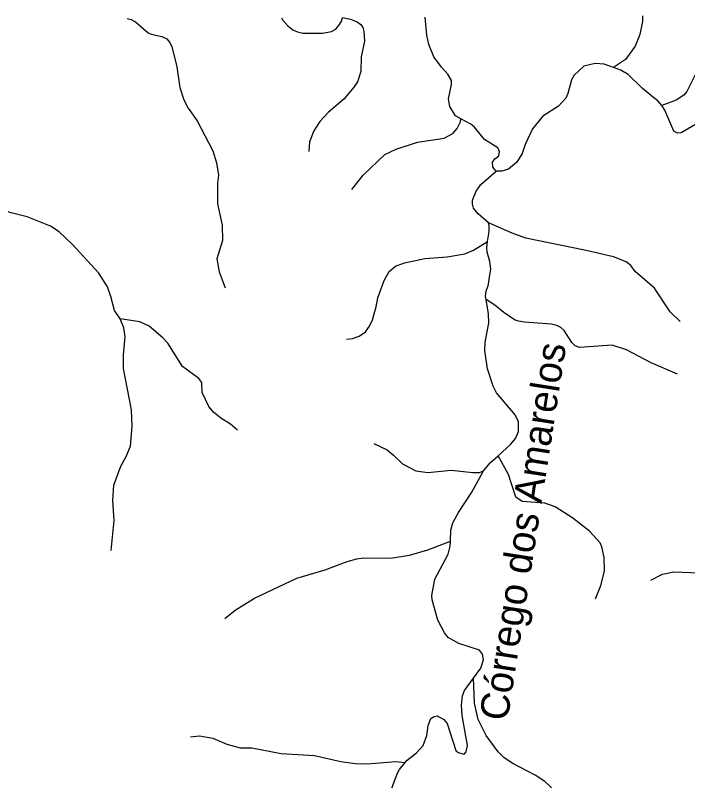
# Model space of a CAD drawing. Extents: x 280.4 to 335.6, y 8893.9 to 8949.5.
# Drawn here: x 293.02 to 297.74, y 8943.96 to 8949.33 of the extents above; entities that cross this region are included whole.
import ezdxf
from ezdxf.enums import TextEntityAlignment as Align

# ---------------------------------------------------------------- set-up
doc = ezdxf.new("R2010")
doc.units = 0
doc.header["$LTSCALE"] = 0.064
doc.linetypes.add('LONG_DASHED', pattern=[7.5, 6, -1.5])
doc.layers.add('61', color=7, linetype='Continuous')
doc.layers.add('7', color=7, linetype='Continuous', lineweight=25)
doc.layers.add('9', color=7, linetype='LONG_DASHED', lineweight=25)

msp = doc.modelspace()

# ---------------------------------------------------------------- linework, layer by layer
at = {"layer": '7'}
for points in [[(293.8085, 8949.3069), (293.8352, 8949.3008), (293.867, 8949.2831), (293.9552, 8949.2082), (293.9757, 8949.1983), (294.052, 8949.1811), (294.0872, 8949.1649), (294.1049, 8949.1417), (294.1208, 8949.1109), (294.1572, 8948.9685), (294.1769, 8948.8231), (294.2053, 8948.7373), (294.2352, 8948.6778), (294.2982, 8948.5895), (294.4092, 8948.3801), (294.4358, 8948.2952), (294.4485, 8948.2089), (294.4423, 8948.152), (294.4425, 8948.0083), (294.4755, 8947.8586), (294.4775, 8947.7513), (294.4376, 8947.622), (294.4535, 8947.5309), (294.4951, 8947.4173)], [(294.8909, 8949.3127), (294.9005, 8949.2957), (294.9349, 8949.256), (294.97, 8949.2278), (295.0028, 8949.2131), (295.0396, 8949.2039), (295.1772, 8949.2036), (295.2411, 8949.2163), (295.2705, 8949.2326), (295.2973, 8949.266), (295.3103, 8949.29), (295.3173, 8949.315)], [(295.3173, 8949.315), (295.3752, 8949.3019), (295.4209, 8949.2834), (295.4461, 8949.266), (295.4612, 8949.2436), (295.4689, 8949.2164), (295.4722, 8949.1477), (295.4482, 8949.0398), (295.4465, 8948.9357), (295.4238, 8948.864), (295.4007, 8948.828), (295.3276, 8948.7426), (295.2169, 8948.6476), (295.1599, 8948.5857), (295.1172, 8948.5191), (295.0857, 8948.4421), (295.082, 8948.3737)], [(296.1471, 8948.6045), (296.1114, 8948.6238), (296.0699, 8948.6894), (296.0624, 8948.743), (296.0827, 8948.8439), (296.0826, 8948.8723), (296.0579, 8948.9167), (296.0132, 8948.9655), (295.9585, 8949.0396), (295.9231, 8949.1243), (295.9106, 8949.1902), (295.8987, 8949.3181)], [(297.2191, 8948.9636), (297.1539, 8948.9862), (297.0904, 8948.9922), (297.0107, 8948.9732), (296.9436, 8948.9093), (296.9248, 8948.8781), (296.8984, 8948.7808), (296.884, 8948.7491), (296.8325, 8948.693), (296.7229, 8948.6231), (296.651, 8948.5336), (296.6003, 8948.4248), (296.5775, 8948.3599), (296.5408, 8948.2991), (296.4823, 8948.2503), (296.4356, 8948.2379), (296.3951, 8948.236)], [(297.5588, 8948.697), (297.5288, 8948.7293), (297.5016, 8948.7523), (297.419, 8948.8194), (297.3212, 8948.9151), (297.2704, 8948.9458), (297.2191, 8948.9636)], [(297.9925, 8948.4193), (297.9413, 8948.4829), (297.9057, 8948.5389), (297.8715, 8948.5714), (297.841, 8948.5789), (297.7942, 8948.5639), (297.6934, 8948.5066), (297.6664, 8948.5034), (297.6409, 8948.5177), (297.5781, 8948.6636), (297.5588, 8948.697)], [(295.3839, 8948.109), (295.4636, 8948.2084), (295.6158, 8948.3532), (295.6955, 8948.391), (295.8432, 8948.4392), (296.0317, 8948.4673), (296.091, 8948.5016), (296.1221, 8948.5361), (296.1462, 8948.5826), (296.1471, 8948.6045)], [(296.3951, 8948.236), (296.3725, 8948.2641), (296.3707, 8948.2989), (296.3872, 8948.3221), (296.4156, 8948.3452), (296.4187, 8948.3745), (296.408, 8948.4), (296.3141, 8948.4581), (296.2446, 8948.5447), (296.219, 8948.5655), (296.1471, 8948.6045)], [(296.3421, 8947.8743), (296.269, 8947.9383), (296.2365, 8947.9763), (296.2288, 8948.0043), (296.2301, 8948.0332), (296.256, 8948.0974), (296.2876, 8948.1442), (296.3951, 8948.236)], [(293.7599, 8947.202), (293.7197, 8947.2591), (293.6947, 8947.3585), (293.6698, 8947.4252), (293.6085, 8947.5218), (293.4238, 8947.7225), (293.3325, 8947.8102), (293.2709, 8947.851), (293.1059, 8947.9175), (292.9845, 8947.9465), (292.8422, 8948.008)], [(296.3342, 8947.743), (296.3466, 8947.814), (296.3468, 8947.8526), (296.3421, 8947.8743)], [(297.6853, 8947.1818), (297.617, 8947.2507), (297.5058, 8947.4162), (297.3707, 8947.534), (297.3396, 8947.5761), (297.3081, 8947.6011), (297.2179, 8947.6349), (297.0266, 8947.6811), (296.6044, 8947.7676), (296.5086, 8947.8012), (296.3755, 8947.8613), (296.3421, 8947.8743)], [(295.3457, 8947.0589), (295.3873, 8947.0623), (295.4358, 8947.0792), (295.4785, 8947.1103), (295.5072, 8947.1484), (295.5294, 8947.1944), (295.5553, 8947.2862), (295.5651, 8947.3485), (295.6095, 8947.471), (295.6458, 8947.5319), (295.6901, 8947.5699), (295.7536, 8947.5947), (295.8954, 8947.6231), (296.0511, 8947.6364), (296.1751, 8947.657), (296.2375, 8947.6824), (296.3342, 8947.743)], [(296.3254, 8947.3377), (296.3217, 8947.36), (296.3251, 8947.3942), (296.3365, 8947.4283), (296.3421, 8947.4453), (296.3517, 8947.5092), (296.3578, 8947.549), (296.3517, 8947.6036), (296.3326, 8947.6692), (296.3294, 8947.7009), (296.3342, 8947.743)], [(296.41, 8946.2402), (296.4994, 8946.3207), (296.531, 8946.3624), (296.5532, 8946.4106), (296.5533, 8946.4787), (296.5284, 8946.5281), (296.3985, 8946.6823), (296.3746, 8946.7276), (296.3345, 8946.8511), (296.3166, 8946.9799), (296.3197, 8947.0343), (296.3453, 8947.1733), (296.3422, 8947.2358), (296.3254, 8947.3377)], [(297.6679, 8946.8125), (297.4834, 8946.893), (297.3107, 8946.9825), (297.2105, 8947.0153), (296.9794, 8946.9999), (296.949, 8947.0111), (296.9256, 8947.0344), (296.8719, 8947.1187), (296.8501, 8947.1406), (296.8222, 8947.1542), (296.7828, 8947.163), (296.5921, 8947.1783), (296.5525, 8947.1842), (296.5239, 8947.1939), (296.449, 8947.2448), (296.3871, 8947.2971), (296.3254, 8947.3377)], [(293.696, 8945.575), (293.716, 8945.7863), (293.7081, 8945.9268), (293.7155, 8946.0337), (293.7637, 8946.1678), (293.8019, 8946.2358), (293.8309, 8946.3076), (293.8441, 8946.4458), (293.8375, 8946.563), (293.7834, 8946.852), (293.7834, 8946.9487), (293.7944, 8947.0737), (293.7854, 8947.1377), (293.7599, 8947.202)], [(294.5809, 8946.4192), (294.5332, 8946.4614), (294.4647, 8946.5042), (294.4125, 8946.5469), (294.3807, 8946.587), (294.3344, 8946.6842), (294.331, 8946.7554), (294.31, 8946.7815), (294.1967, 8946.8665), (294.0938, 8947.0309), (294.0584, 8947.0686), (293.9622, 8947.1492), (293.8981, 8947.1793), (293.7599, 8947.202)], [(295.5383, 8946.3274), (295.6308, 8946.2811), (295.6763, 8946.2455), (295.7383, 8946.1838), (295.833, 8946.1352), (295.9177, 8946.1234), (296.0806, 8946.1394), (296.2312, 8946.1234), (296.2782, 8946.1237), (296.3066, 8946.1359)], [(296.3066, 8946.1359), (296.3571, 8946.1926), (296.41, 8946.2402)], [(297.0916, 8945.2379), (297.1306, 8945.3315), (297.1547, 8945.4301), (297.1544, 8945.526), (297.1374, 8945.6007), (297.125, 8945.6288), (297.0514, 8945.711), (296.9339, 8945.802), (296.8103, 8945.8813), (296.7362, 8945.9089), (296.578, 8945.9204), (296.5342, 8945.9512), (296.4825, 8946.1081), (296.41, 8946.2402)], [(296.0746, 8945.6413), (296.0771, 8945.7187), (296.0918, 8945.7698), (296.1326, 8945.8436), (296.2262, 8945.9858), (296.3066, 8946.1359)], [(297.4808, 8945.3688), (297.5627, 8945.4097), (297.6418, 8945.4274), (297.8161, 8945.4199), (297.8633, 8945.4305), (297.8871, 8945.4428), (297.9353, 8945.4953), (298.0135, 8945.6548), (298.0654, 8945.7296), (298.105, 8945.7737), (298.1819, 8945.8375), (298.3065, 8945.8792), (298.4471, 8945.9897)], [(294.4924, 8945.1), (294.5661, 8945.1568), (294.7007, 8945.2419), (294.9989, 8945.3813), (295.1965, 8945.4404), (295.35, 8945.4995), (295.4188, 8945.5184), (295.4643, 8945.5236), (295.6538, 8945.5222), (295.7882, 8945.5444), (295.9166, 8945.5807), (296.0746, 8945.6413)], [(295.9869, 8945.0878), (295.9472, 8945.2311), (295.9441, 8945.2605), (295.9648, 8945.375), (296.0583, 8945.5504), (296.0735, 8945.6058), (296.0746, 8945.6413)], [(296.2367, 8944.6803), (296.2885, 8944.7498), (296.3067, 8944.8081), (296.3008, 8944.8491), (296.278, 8944.8759), (296.1349, 8944.9238), (296.0595, 8944.9659), (296.0337, 8944.9991), (295.9869, 8945.0878)], [(295.7589, 8944.0889), (295.7721, 8944.1049), (295.8381, 8944.1577), (295.8841, 8944.2086), (295.9101, 8944.2772), (295.9198, 8944.3476), (295.9366, 8944.3979), (295.9618, 8944.4121), (295.9832, 8944.4152), (296.0286, 8944.3914), (296.0534, 8944.3635), (296.112, 8944.1742), (296.1296, 8944.158), (296.1715, 8944.1475), (296.1864, 8944.1639), (296.1948, 8944.2092), (296.1568, 8944.4179), (296.1535, 8944.4907), (296.1596, 8944.5577), (296.1728, 8944.5945), (296.2367, 8944.6803)], [(297.4542, 8943.0821), (297.4388, 8943.0915), (297.4099, 8943.1274), (297.3833, 8943.1991), (297.3847, 8943.2712), (297.3748, 8943.3583), (297.3558, 8943.415), (297.3242, 8943.4694), (297.2656, 8943.5279), (297.0394, 8943.6942), (296.8514, 8943.8473), (296.7371, 8943.9548), (296.67, 8943.9996), (296.5072, 8944.0853), (296.45, 8944.124), (296.4103, 8944.1627), (296.3252, 8944.2788), (296.2703, 8944.3899), (296.2431, 8944.5058), (296.2367, 8944.6803)], [(294.253, 8944.2689), (294.3143, 8944.2763), (294.4089, 8944.2606), (294.5075, 8944.2183), (294.6015, 8944.1918), (294.6815, 8944.1915), (294.8892, 8944.1525), (295.1222, 8944.1373), (295.3061, 8944.0962), (295.4082, 8944.0829), (295.492, 8944.0797), (295.6921, 8944.0955), (295.7589, 8944.0889)], [(295.54, 8943.5802), (295.5698, 8943.634), (295.572, 8943.6636), (295.7012, 8944.0099), (295.7174, 8944.0387), (295.7589, 8944.0889)]]:
    msp.add_lwpolyline(points, dxfattribs=at)
at = {"layer": '9'}
for points in [[(297.4218, 8949.3262), (297.4219, 8949.3239), (297.4231, 8949.286), (297.4041, 8949.1964), (297.3704, 8949.1126), (297.3032, 8949.0199), (297.2191, 8948.9636)], [(298.1483, 8949.33), (298.1391, 8949.3154), (298.0725, 8949.2439), (297.8659, 8949.0957), (297.8105, 8948.9908), (297.7937, 8948.9173), (297.7339, 8948.7949), (297.7123, 8948.7698), (297.6582, 8948.7341), (297.5588, 8948.697)]]:
    msp.add_lwpolyline(points, dxfattribs=at)

# ---------------------------------------------------------------- texts
at = {"layer": '61'}
msp.add_text('Córrego dos Amarelos', height=0.2, rotation=81.119, dxfattribs=at).set_placement((296.6812, 8945.6952), align=Align.CENTER)

doc.saveas('drawing.dxf')
